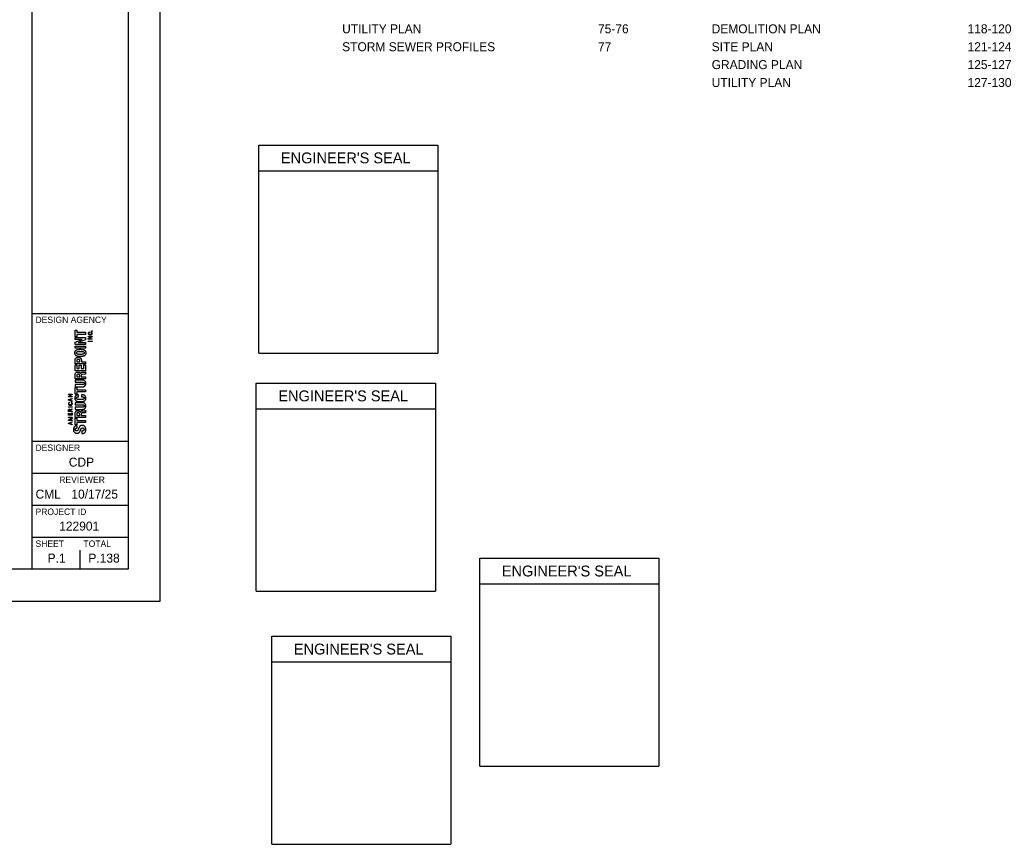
# Model space of a CAD drawing. Extents: x -21.9 to 47.3, y 14.1 to 48.7.
# Drawn here: x 31.81 to 47.3, y 22.94 to 35.82 of the extents above; entities that cross this region are included whole.
import ezdxf

# ---------------------------------------------------------------- set-up
doc = ezdxf.new("R2010")
doc.units = 0
for name, color, linetype in [('SH_Border', 7, 'Continuous'), ('SH_Cut_Line', 7, 'Continuous'), ('SH_Data', 7, 'Continuous'), ('SH_Text', 7, 'Continuous')]:
    doc.layers.add(name, color=color, linetype=linetype)

msp = doc.modelspace()

# ---------------------------------------------------------------- linework, layer by layer
at = {"layer": 'SH_Border'}
for p, q in [((32, 27.233), (32, 48.233)), ((32, 31.233), (33.5, 31.233)), ((32, 29.233), (33.5, 29.233)), ((32, 28.733), (33.5, 28.733)), ((32, 28.233), (33.5, 28.233)), ((32, 27.733), (33.5, 27.733))]:
    msp.add_line(p, q, dxfattribs=at)
msp.add_lwpolyline([(1.5, 48.233), (33.5, 48.233), (33.5, 27.233), (1.5, 27.233)], close=True, dxfattribs=at)
at = {"layer": 'SH_Cut_Line'}
msp.add_lwpolyline([(0, 26.733), (34, 26.733), (34, 48.733), (0, 48.733)], close=True, dxfattribs=at)
at = {"layer": 'SH_Data'}
for p, q in [((35.542, 30.613), (35.542, 33.863)), ((35.542, 33.863), (38.342, 33.863)), ((38.342, 33.863), (38.342, 30.613)), ((35.542, 33.463), (38.342, 33.463)), ((35.542, 30.613), (38.342, 30.613)), ((32.75, 30.233), (32.75, 30.233)), ((32.75, 30.233), (32.75, 30.233)), ((35.502, 26.893), (35.502, 30.143)), ((35.502, 30.143), (38.302, 30.143)), ((38.302, 30.143), (38.302, 26.893)), ((35.502, 29.743), (38.302, 29.743)), ((32.75, 27.233), (32.75, 27.533)), ((32.375, 27.408), (32.375, 27.408)), ((38.996, 24.156), (38.996, 27.406)), ((38.996, 27.406), (41.796, 27.406)), ((41.796, 27.406), (41.796, 24.156)), ((38.996, 27.006), (41.796, 27.006)), ((35.502, 26.893), (38.302, 26.893)), ((35.744, 22.936), (35.744, 26.186)), ((35.744, 26.186), (38.544, 26.186)), ((38.544, 26.186), (38.544, 22.936)), ((35.744, 25.786), (38.544, 25.786)), ((38.996, 24.156), (41.796, 24.156)), ((35.744, 22.936), (38.544, 22.936))]:
    msp.add_line(p, q, dxfattribs=at)
for points in [[(32.67, 30.973), (32.697, 30.973), (32.697, 30.937), (32.833, 30.937), (32.833, 30.904), (32.697, 30.904), (32.697, 30.868), (32.67, 30.868), (32.67, 30.973)], [(32.67, 30.785), (32.781, 30.825), (32.781, 30.825), (32.67, 30.825), (32.67, 30.855), (32.833, 30.855), (32.833, 30.818), (32.719, 30.777), (32.719, 30.777), (32.833, 30.777), (32.833, 30.747), (32.67, 30.747), (32.67, 30.785)], [(32.875, 30.829), (32.875, 30.839), (32.925, 30.867), (32.925, 30.867), (32.875, 30.867), (32.875, 30.873), (32.935, 30.873), (32.935, 30.867), (32.88, 30.835), (32.88, 30.835), (32.935, 30.835), (32.935, 30.829), (32.875, 30.829)], [(32.935, 30.951), (32.927, 30.951), (32.927, 30.958), (32.935, 30.958), (32.935, 30.951)], [(32.833, 30.69), (32.67, 30.69), (32.67, 30.723), (32.833, 30.723), (32.833, 30.69)], [(32.875, 30.795), (32.875, 30.8), (32.935, 30.8), (32.935, 30.795), (32.875, 30.795)], [(32.833, 30.445), (32.67, 30.445), (32.67, 30.502)], [(32.67, 30.427), (32.697, 30.427), (32.697, 30.369), (32.735, 30.369), (32.735, 30.424), (32.762, 30.424), (32.762, 30.369), (32.806, 30.369), (32.806, 30.429), (32.833, 30.429), (32.833, 30.336), (32.67, 30.336), (32.67, 30.427)], [(32.694, 30.478), (32.743, 30.478), (32.743, 30.492)], [(32.694, 30.492), (32.694, 30.478)], [(32.768, 30.495), (32.768, 30.478), (32.833, 30.478), (32.833, 30.445)], [(32.833, 30.21), (32.67, 30.21), (32.67, 30.271)], [(32.694, 30.258), (32.694, 30.243)], [(32.694, 30.243), (32.741, 30.243), (32.741, 30.256)], [(32.752, 30.287), (32.752, 30.287)], [(32.764, 30.26), (32.764, 30.243), (32.833, 30.243), (32.833, 30.21)], [(32.816, 30.281), (32.784, 30.28)], [(32.832, 30.321), (32.833, 30.321), (32.833, 30.285)], [(32.67, 30.075), (32.697, 30.075), (32.697, 30.039), (32.833, 30.039), (32.833, 30.006), (32.697, 30.006), (32.697, 29.97), (32.67, 29.97), (32.67, 30.075)], [(32.565, 29.927), (32.565, 29.936), (32.615, 29.965), (32.615, 29.965), (32.565, 29.965), (32.565, 29.97), (32.625, 29.97), (32.625, 29.965), (32.569, 29.933), (32.569, 29.933), (32.625, 29.933), (32.625, 29.927), (32.565, 29.927)], [(32.625, 29.858), (32.565, 29.877), (32.565, 29.886), (32.625, 29.904), (32.625, 29.899), (32.605, 29.893), (32.605, 29.87), (32.625, 29.864), (32.625, 29.858)], [(32.565, 29.767), (32.565, 29.772), (32.625, 29.772), (32.625, 29.767), (32.565, 29.767)], [(32.601, 29.872), (32.601, 29.891), (32.569, 29.882), (32.569, 29.881), (32.601, 29.872)], [(32.596, 29.725), (32.625, 29.74), (32.625, 29.734), (32.597, 29.72), (32.597, 29.704), (32.625, 29.704), (32.625, 29.699), (32.565, 29.699), (32.565, 29.719)], [(32.625, 29.641), (32.565, 29.641), (32.565, 29.675), (32.569, 29.675), (32.569, 29.646), (32.591, 29.646), (32.591, 29.667), (32.596, 29.667), (32.596, 29.646), (32.62, 29.646), (32.62, 29.676), (32.625, 29.676), (32.625, 29.641)], [(32.625, 29.56), (32.565, 29.56), (32.565, 29.569), (32.615, 29.586), (32.615, 29.586), (32.565, 29.603), (32.565, 29.612), (32.625, 29.612), (32.625, 29.607), (32.569, 29.607), (32.569, 29.606), (32.625, 29.589), (32.625, 29.583), (32.569, 29.565), (32.569, 29.565), (32.625, 29.565), (32.625, 29.56)], [(32.569, 29.704), (32.593, 29.704), (32.593, 29.719)], [(32.569, 29.719), (32.569, 29.704)], [(32.833, 29.607), (32.67, 29.607), (32.67, 29.668)], [(32.694, 29.655), (32.694, 29.639)], [(32.694, 29.639), (32.741, 29.639), (32.741, 29.653)], [(32.752, 29.684), (32.752, 29.684)], [(32.764, 29.657), (32.764, 29.639), (32.833, 29.639), (32.833, 29.607)], [(32.816, 29.678), (32.784, 29.677)], [(32.832, 29.718), (32.833, 29.718), (32.833, 29.682)], [(32.625, 29.491), (32.565, 29.51), (32.565, 29.518), (32.625, 29.537), (32.625, 29.531), (32.605, 29.525), (32.605, 29.503), (32.625, 29.497), (32.625, 29.491)], [(32.601, 29.504), (32.601, 29.524), (32.569, 29.514), (32.569, 29.514), (32.601, 29.504)], [(32.67, 29.593), (32.697, 29.593), (32.697, 29.558), (32.833, 29.558), (32.833, 29.525), (32.697, 29.525), (32.697, 29.489), (32.67, 29.489), (32.67, 29.593)]]:
    msp.add_lwpolyline(points, dxfattribs=at)
for points in [[(32.893, 30.934), (32.889, 30.933), (32.885, 30.931), (32.883, 30.928), (32.88, 30.926), (32.879, 30.923), (32.879, 30.919), (32.879, 30.916), (32.88, 30.914), (32.881, 30.912), (32.882, 30.91), (32.884, 30.908), (32.887, 30.907), (32.889, 30.905), (32.892, 30.904), (32.895, 30.903), (32.898, 30.903), (32.902, 30.902), (32.905, 30.902), (32.909, 30.902), (32.912, 30.903), (32.915, 30.903), (32.919, 30.904), (32.921, 30.905), (32.924, 30.907), (32.926, 30.908), (32.928, 30.91), (32.929, 30.912), (32.931, 30.914), (32.931, 30.917), (32.931, 30.92), (32.931, 30.922), (32.931, 30.924), (32.93, 30.926), (32.929, 30.928), (32.928, 30.929), (32.927, 30.93), (32.926, 30.931), (32.924, 30.932), (32.922, 30.933), (32.921, 30.934), (32.919, 30.935), (32.917, 30.935), (32.917, 30.935), (32.918, 30.94), (32.918, 30.94), (32.92, 30.94), (32.923, 30.939), (32.925, 30.938), (32.927, 30.937), (32.929, 30.935), (32.931, 30.934), (32.932, 30.932), (32.934, 30.93), (32.934, 30.928), (32.935, 30.926), (32.936, 30.923), (32.936, 30.92), (32.936, 30.916), (32.935, 30.913), (32.934, 30.91), (32.932, 30.907), (32.93, 30.905), (32.927, 30.903), (32.925, 30.901), (32.921, 30.9), (32.918, 30.899), (32.914, 30.898), (32.91, 30.897), (32.905, 30.897), (32.901, 30.897), (32.896, 30.898), (32.893, 30.899), (32.889, 30.9), (32.886, 30.901), (32.883, 30.903), (32.88, 30.905), (32.878, 30.907), (32.877, 30.91), (32.875, 30.913), (32.875, 30.916), (32.875, 30.92), (32.875, 30.923), (32.875, 30.925), (32.876, 30.927), (32.877, 30.929), (32.878, 30.931), (32.88, 30.932), (32.881, 30.934), (32.883, 30.935), (32.885, 30.936), (32.887, 30.937), (32.889, 30.938), (32.892, 30.939), (32.892, 30.939), (32.893, 30.934), (32.893, 30.934)], [(32.751, 30.559), (32.739, 30.559), (32.727, 30.56), (32.717, 30.561), (32.706, 30.562), (32.697, 30.565), (32.69, 30.568), (32.682, 30.572), (32.677, 30.578), (32.672, 30.585), (32.668, 30.593), (32.666, 30.603), (32.666, 30.615), (32.666, 30.627), (32.668, 30.637), (32.672, 30.645), (32.677, 30.652), (32.682, 30.657), (32.69, 30.661), (32.697, 30.665), (32.706, 30.668), (32.717, 30.669), (32.727, 30.67), (32.739, 30.671), (32.751, 30.671), (32.758, 30.671), (32.764, 30.67), (32.771, 30.67)], [(32.67, 30.502), (32.67, 30.511), (32.671, 30.518), (32.674, 30.524), (32.677, 30.529), (32.68, 30.534), (32.685, 30.537), (32.689, 30.541), (32.695, 30.543), (32.701, 30.545), (32.706, 30.546), (32.712, 30.547), (32.719, 30.547), (32.727, 30.547), (32.734, 30.546), (32.741, 30.543), (32.747, 30.541), (32.752, 30.537), (32.756, 30.533), (32.76, 30.528), (32.763, 30.523), (32.765, 30.517), (32.767, 30.51), (32.768, 30.503), (32.768, 30.495)], [(32.751, 30.592), (32.762, 30.592), (32.771, 30.592), (32.779, 30.593), (32.787, 30.593), (32.793, 30.594), (32.798, 30.596), (32.803, 30.598), (32.806, 30.6), (32.808, 30.603), (32.81, 30.606), (32.812, 30.61), (32.812, 30.615), (32.812, 30.62), (32.81, 30.624), (32.808, 30.627), (32.806, 30.63), (32.803, 30.632), (32.798, 30.634), (32.793, 30.635), (32.787, 30.636), (32.779, 30.637), (32.771, 30.638), (32.762, 30.638), (32.751, 30.638), (32.74, 30.638), (32.731, 30.638), (32.723, 30.637), (32.716, 30.636), (32.709, 30.635), (32.704, 30.634), (32.7, 30.632), (32.696, 30.63), (32.694, 30.627), (32.692, 30.624), (32.691, 30.62), (32.691, 30.615), (32.691, 30.61), (32.692, 30.606), (32.694, 30.603), (32.696, 30.6), (32.7, 30.598), (32.704, 30.596), (32.709, 30.594), (32.716, 30.593), (32.723, 30.593), (32.731, 30.592), (32.74, 30.592), (32.751, 30.592)], [(32.771, 30.67), (32.776, 30.67), (32.781, 30.669), (32.785, 30.669), (32.796, 30.668), (32.805, 30.665), (32.812, 30.661), (32.82, 30.657), (32.825, 30.652), (32.83, 30.645), (32.834, 30.637), (32.836, 30.627), (32.836, 30.615), (32.836, 30.603), (32.834, 30.593), (32.83, 30.585), (32.825, 30.578), (32.82, 30.572), (32.812, 30.568), (32.805, 30.565), (32.796, 30.562), (32.785, 30.561), (32.775, 30.56), (32.763, 30.559), (32.751, 30.559)], [(32.743, 30.492), (32.743, 30.499), (32.741, 30.504), (32.737, 30.508), (32.733, 30.512), (32.727, 30.514), (32.719, 30.514), (32.711, 30.514), (32.705, 30.513), (32.7, 30.509), (32.696, 30.506), (32.694, 30.5), (32.694, 30.492)], [(32.67, 30.271), (32.67, 30.284), (32.673, 30.295), (32.68, 30.303), (32.687, 30.31), (32.698, 30.314), (32.712, 30.314), (32.723, 30.314), (32.732, 30.312), (32.739, 30.308), (32.745, 30.303), (32.75, 30.296), (32.752, 30.287)], [(32.741, 30.256), (32.741, 30.265), (32.739, 30.271), (32.735, 30.275), (32.732, 30.279), (32.725, 30.281), (32.717, 30.281), (32.702, 30.281), (32.694, 30.274), (32.694, 30.258)], [(32.752, 30.287), (32.753, 30.293), (32.755, 30.297), (32.757, 30.301), (32.759, 30.304), (32.762, 30.307), (32.766, 30.309), (32.769, 30.311), (32.774, 30.312), (32.78, 30.312), (32.786, 30.313), (32.794, 30.313), (32.802, 30.314), (32.811, 30.314), (32.818, 30.314), (32.822, 30.315), (32.827, 30.316), (32.83, 30.318), (32.832, 30.321)], [(32.784, 30.28), (32.778, 30.28), (32.773, 30.278), (32.769, 30.275), (32.766, 30.272), (32.764, 30.267), (32.764, 30.26)], [(32.833, 30.285), (32.831, 30.284), (32.828, 30.282), (32.825, 30.282), (32.822, 30.282), (32.819, 30.281), (32.816, 30.281)], [(32.67, 30.119), (32.67, 30.119), (32.783, 30.119), (32.783, 30.119), (32.787, 30.119), (32.791, 30.119), (32.795, 30.119), (32.798, 30.12), (32.801, 30.121), (32.803, 30.122), (32.806, 30.124), (32.808, 30.126), (32.809, 30.128), (32.811, 30.131), (32.812, 30.134), (32.812, 30.138), (32.812, 30.142), (32.811, 30.145), (32.809, 30.147), (32.808, 30.15), (32.806, 30.152), (32.803, 30.153), (32.801, 30.155), (32.798, 30.156), (32.795, 30.156), (32.791, 30.157), (32.787, 30.157), (32.783, 30.157), (32.783, 30.157), (32.67, 30.157), (32.67, 30.157), (32.67, 30.157), (32.67, 30.19), (32.67, 30.19), (32.67, 30.19), (32.783, 30.19), (32.783, 30.19), (32.794, 30.19), (32.802, 30.189), (32.809, 30.186), (32.816, 30.183), (32.821, 30.179), (32.825, 30.174), (32.829, 30.169), (32.832, 30.164), (32.834, 30.157), (32.835, 30.151), (32.836, 30.145), (32.836, 30.138), (32.836, 30.131), (32.835, 30.125), (32.834, 30.118), (32.833, 30.112), (32.83, 30.107), (32.826, 30.102), (32.822, 30.097), (32.817, 30.093), (32.81, 30.09), (32.803, 30.087), (32.794, 30.086), (32.783, 30.086), (32.783, 30.086), (32.67, 30.086), (32.67, 30.086), (32.67, 30.086), (32.67, 30.119), (32.67, 30.119)], [(32.725, 29.927), (32.713, 29.927), (32.704, 29.925), (32.699, 29.923), (32.693, 29.92), (32.691, 29.915), (32.691, 29.907), (32.691, 29.903), (32.692, 29.9), (32.694, 29.897), (32.696, 29.894), (32.7, 29.892), (32.705, 29.891), (32.71, 29.889), (32.716, 29.888), (32.724, 29.887), (32.732, 29.887), (32.742, 29.886), (32.753, 29.886), (32.766, 29.886), (32.776, 29.887), (32.783, 29.888), (32.791, 29.889), (32.797, 29.89), (32.801, 29.892), (32.805, 29.893), (32.808, 29.896), (32.809, 29.898), (32.811, 29.901), (32.812, 29.904), (32.812, 29.908), (32.812, 29.911), (32.811, 29.913), (32.81, 29.916), (32.809, 29.918), (32.807, 29.921), (32.804, 29.922), (32.801, 29.924), (32.797, 29.926), (32.792, 29.927), (32.786, 29.928), (32.779, 29.928), (32.77, 29.928), (32.77, 29.928), (32.77, 29.961), (32.77, 29.961), (32.779, 29.961), (32.787, 29.961), (32.795, 29.959), (32.803, 29.958), (32.81, 29.955), (32.816, 29.952), (32.822, 29.948), (32.827, 29.943), (32.831, 29.936), (32.834, 29.929), (32.836, 29.92), (32.836, 29.909), (32.836, 29.897), (32.834, 29.887), (32.83, 29.88), (32.825, 29.872), (32.82, 29.867), (32.812, 29.863), (32.805, 29.859), (32.796, 29.856), (32.785, 29.855), (32.775, 29.854), (32.763, 29.854), (32.751, 29.854), (32.739, 29.854), (32.727, 29.854), (32.717, 29.855), (32.706, 29.856), (32.697, 29.859), (32.69, 29.863), (32.682, 29.867), (32.677, 29.872), (32.672, 29.88), (32.668, 29.887), (32.666, 29.897), (32.666, 29.909), (32.666, 29.921), (32.668, 29.93), (32.672, 29.937), (32.676, 29.944), (32.681, 29.949), (32.687, 29.952), (32.692, 29.956), (32.699, 29.958), (32.706, 29.958), (32.712, 29.959), (32.719, 29.96), (32.725, 29.96), (32.725, 29.96), (32.725, 29.927), (32.725, 29.927)], [(32.582, 29.834), (32.578, 29.833), (32.575, 29.831), (32.572, 29.829), (32.57, 29.826), (32.569, 29.823), (32.569, 29.82), (32.569, 29.817), (32.569, 29.814), (32.571, 29.812), (32.572, 29.81), (32.574, 29.808), (32.576, 29.807), (32.579, 29.806), (32.581, 29.804), (32.585, 29.804), (32.588, 29.803), (32.591, 29.803), (32.595, 29.803), (32.598, 29.803), (32.602, 29.803), (32.605, 29.804), (32.608, 29.804), (32.611, 29.806), (32.613, 29.807), (32.616, 29.808), (32.618, 29.81), (32.619, 29.812), (32.62, 29.815), (32.621, 29.817), (32.621, 29.82), (32.621, 29.823), (32.62, 29.825), (32.62, 29.826), (32.619, 29.828), (32.618, 29.83), (32.617, 29.831), (32.615, 29.832), (32.614, 29.833), (32.612, 29.834), (32.61, 29.834), (32.608, 29.835), (32.606, 29.835), (32.606, 29.835), (32.607, 29.841), (32.607, 29.841), (32.61, 29.84), (32.612, 29.839), (32.615, 29.838), (32.617, 29.837), (32.619, 29.836), (32.62, 29.834), (32.622, 29.833), (32.623, 29.831), (32.624, 29.828), (32.625, 29.826), (32.625, 29.823), (32.625, 29.82), (32.625, 29.817), (32.625, 29.813), (32.623, 29.811), (32.622, 29.808), (32.62, 29.805), (32.617, 29.803), (32.614, 29.802), (32.611, 29.8), (32.607, 29.799), (32.604, 29.798), (32.599, 29.797), (32.595, 29.797), (32.59, 29.797), (32.586, 29.798), (32.582, 29.799), (32.579, 29.8), (32.575, 29.802), (32.573, 29.803), (32.57, 29.805), (32.568, 29.808), (32.566, 29.811), (32.565, 29.813), (32.564, 29.817), (32.564, 29.82), (32.564, 29.823), (32.565, 29.825), (32.566, 29.827), (32.566, 29.83), (32.568, 29.831), (32.569, 29.833), (32.571, 29.834), (32.572, 29.836), (32.575, 29.837), (32.577, 29.838), (32.579, 29.839), (32.581, 29.839), (32.581, 29.839), (32.582, 29.834), (32.582, 29.834)], [(32.67, 29.766), (32.67, 29.766), (32.783, 29.766), (32.783, 29.766), (32.787, 29.766), (32.791, 29.766), (32.795, 29.767), (32.798, 29.767), (32.801, 29.768), (32.803, 29.77), (32.806, 29.771), (32.808, 29.773), (32.809, 29.776), (32.811, 29.778), (32.812, 29.781), (32.812, 29.785), (32.812, 29.789), (32.811, 29.792), (32.809, 29.795), (32.808, 29.797), (32.806, 29.799), (32.803, 29.801), (32.801, 29.802), (32.798, 29.803), (32.795, 29.804), (32.791, 29.804), (32.787, 29.804), (32.783, 29.804), (32.783, 29.804), (32.67, 29.804), (32.67, 29.804), (32.67, 29.804), (32.67, 29.837), (32.67, 29.837), (32.67, 29.837), (32.783, 29.837), (32.783, 29.837), (32.794, 29.837), (32.802, 29.836), (32.809, 29.833), (32.816, 29.83), (32.821, 29.826), (32.825, 29.821), (32.829, 29.816), (32.832, 29.811), (32.834, 29.805), (32.835, 29.798), (32.836, 29.792), (32.836, 29.785), (32.836, 29.778), (32.835, 29.772), (32.834, 29.766), (32.833, 29.76), (32.83, 29.754), (32.826, 29.749), (32.822, 29.744), (32.817, 29.74), (32.81, 29.737), (32.803, 29.735), (32.794, 29.733), (32.783, 29.733), (32.783, 29.733), (32.67, 29.733), (32.67, 29.733), (32.67, 29.733), (32.67, 29.766), (32.67, 29.766)], [(32.565, 29.719), (32.565, 29.725), (32.566, 29.73), (32.569, 29.733), (32.572, 29.736), (32.576, 29.738), (32.581, 29.738), (32.585, 29.738), (32.588, 29.737), (32.591, 29.735), (32.593, 29.733), (32.595, 29.729), (32.596, 29.725)], [(32.593, 29.719), (32.593, 29.723), (32.592, 29.726), (32.59, 29.729), (32.588, 29.731), (32.585, 29.732), (32.581, 29.732), (32.577, 29.732), (32.575, 29.731), (32.573, 29.729), (32.57, 29.727), (32.569, 29.723), (32.569, 29.719)], [(32.67, 29.668), (32.67, 29.681), (32.673, 29.692), (32.68, 29.7), (32.687, 29.707), (32.698, 29.711), (32.712, 29.711), (32.723, 29.711), (32.732, 29.709), (32.739, 29.704), (32.745, 29.7), (32.75, 29.693), (32.752, 29.684)], [(32.741, 29.653), (32.741, 29.661), (32.739, 29.667), (32.735, 29.672), (32.732, 29.676), (32.725, 29.678), (32.717, 29.678), (32.702, 29.678), (32.694, 29.671), (32.694, 29.655)], [(32.752, 29.684), (32.753, 29.69), (32.755, 29.694), (32.757, 29.697), (32.759, 29.701), (32.762, 29.703), (32.766, 29.705), (32.769, 29.707), (32.774, 29.709), (32.78, 29.709), (32.786, 29.71), (32.794, 29.71), (32.802, 29.71), (32.811, 29.71), (32.818, 29.711), (32.822, 29.712), (32.827, 29.713), (32.83, 29.715), (32.832, 29.718)], [(32.784, 29.677), (32.778, 29.677), (32.773, 29.675), (32.769, 29.672), (32.766, 29.669), (32.764, 29.664), (32.764, 29.657)], [(32.833, 29.682), (32.831, 29.68), (32.828, 29.679), (32.825, 29.679), (32.822, 29.678), (32.819, 29.678), (32.816, 29.678)], [(32.775, 29.395), (32.775, 29.395), (32.781, 29.395), (32.781, 29.395), (32.785, 29.395), (32.789, 29.395), (32.793, 29.396), (32.796, 29.396), (32.799, 29.398), (32.801, 29.4), (32.804, 29.402), (32.806, 29.404), (32.807, 29.407), (32.809, 29.41), (32.809, 29.414), (32.809, 29.419), (32.809, 29.425), (32.807, 29.43), (32.804, 29.435), (32.8, 29.439), (32.794, 29.442), (32.786, 29.442), (32.782, 29.442), (32.779, 29.441), (32.776, 29.44), (32.773, 29.439), (32.77, 29.437), (32.767, 29.434), (32.765, 29.432), (32.763, 29.428), (32.761, 29.424), (32.759, 29.42), (32.757, 29.415), (32.755, 29.408), (32.752, 29.4), (32.749, 29.393), (32.745, 29.387), (32.742, 29.381), (32.738, 29.376), (32.734, 29.372), (32.73, 29.368), (32.725, 29.365), (32.719, 29.363), (32.713, 29.361), (32.706, 29.36), (32.699, 29.36), (32.68, 29.36), (32.667, 29.365), (32.658, 29.375), (32.649, 29.385), (32.644, 29.399), (32.644, 29.417), (32.644, 29.426), (32.645, 29.433), (32.647, 29.44), (32.649, 29.447), (32.651, 29.453), (32.656, 29.458), (32.66, 29.463), (32.665, 29.467), (32.671, 29.47), (32.677, 29.473), (32.685, 29.474), (32.694, 29.474), (32.694, 29.474), (32.699, 29.474), (32.699, 29.474), (32.699, 29.474), (32.699, 29.439), (32.699, 29.439), (32.69, 29.439), (32.683, 29.437), (32.679, 29.434), (32.674, 29.431), (32.671, 29.426), (32.671, 29.418), (32.671, 29.414), (32.672, 29.411), (32.673, 29.408), (32.675, 29.405), (32.676, 29.403), (32.678, 29.402), (32.68, 29.4), (32.682, 29.399), (32.685, 29.398), (32.688, 29.398), (32.69, 29.397), (32.693, 29.397), (32.699, 29.397), (32.704, 29.399), (32.707, 29.401), (32.711, 29.403), (32.715, 29.409), (32.718, 29.417), (32.718, 29.417), (32.731, 29.445), (32.731, 29.445), (32.734, 29.452), (32.737, 29.458), (32.74, 29.463), (32.744, 29.467), (32.747, 29.471), (32.751, 29.473), (32.755, 29.476), (32.76, 29.478), (32.764, 29.479), (32.769, 29.48), (32.774, 29.481), (32.78, 29.481), (32.799, 29.481), (32.814, 29.475), (32.823, 29.464), (32.832, 29.452), (32.837, 29.436), (32.837, 29.416), (32.837, 29.395), (32.832, 29.38), (32.823, 29.371), (32.813, 29.362), (32.8, 29.357), (32.783, 29.357), (32.783, 29.357), (32.775, 29.357), (32.775, 29.357), (32.775, 29.357), (32.775, 29.395), (32.775, 29.395)]]:
    msp.add_open_spline(points, degree=3, dxfattribs=at)

# ---------------------------------------------------------------- texts
for s, height, p in [("ENGINEER'S SEAL", 0.17, (35.887, 33.578)), ('DESIGN AGENCY', 0.1, (32.05, 31.083)), ("ENGINEER'S SEAL", 0.17, (35.847, 29.858)), ('DESIGNER', 0.1, (32.05, 29.083)), ('CDP', 0.14, (32.571, 28.838)), ('REVIEWER', 0.1, (32.422, 28.583)), ('CML', 0.14, (32.051, 28.338)), ('10/17/25', 0.14, (32.611, 28.338)), ('PROJECT ID', 0.1, (32.05, 28.083)), ('122901', 0.14, (32.421, 27.838)), ('SHEET', 0.1, (32.05, 27.583)), ('TOTAL', 0.1, (32.8, 27.583)), ('P.1', 0.14, (32.24, 27.338)), ('P.138', 0.14, (32.877, 27.338)), ("ENGINEER'S SEAL", 0.17, (39.34, 27.121)), ("ENGINEER'S SEAL", 0.17, (36.089, 25.901))]:
    msp.add_text(s, height=height, dxfattribs=at).set_placement(p)
at = {"layer": 'SH_Text'}
for s, p in [('UTILITY PLAN', (36.844, 35.611)), ('75-76', (40.844, 35.611)), ('DEMOLITION PLAN', (42.621, 35.611)), ('118-120', (46.621, 35.611)), ('STORM SEWER PROFILES', (36.844, 35.331)), ('77', (40.844, 35.331)), ('SITE PLAN', (42.621, 35.331)), ('121-124', (46.621, 35.331)), ('GRADING PLAN', (42.621, 35.051)), ('125-127', (46.621, 35.051)), ('UTILITY PLAN', (42.621, 34.771)), ('127-130', (46.621, 34.771))]:
    msp.add_text(s, height=0.14, dxfattribs=at).set_placement(p)

doc.saveas('drawing.dxf')
